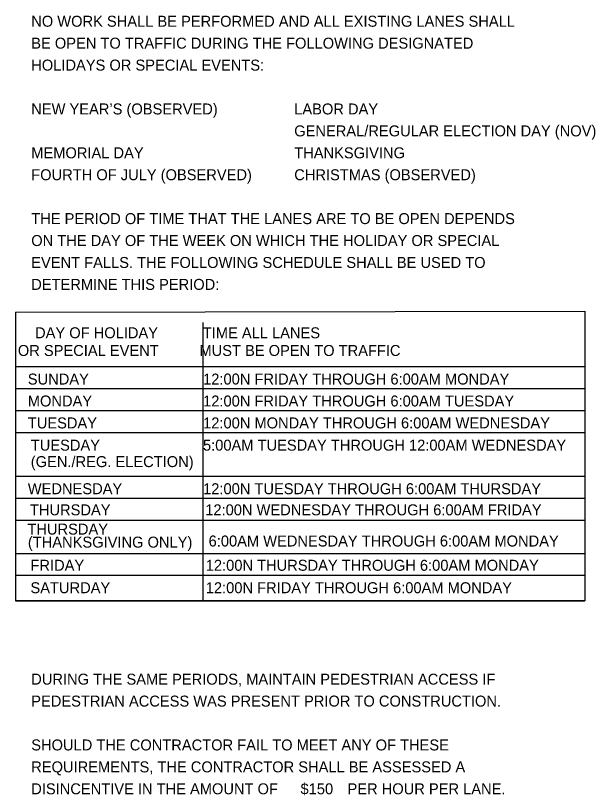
# Model space of a CAD drawing. Extents: x 0 to 34, y 0 to 33.4.
# Drawn here: x 9.62 to 17.03, y 23.47 to 33.42 of the extents above; entities that cross this region are included whole.
import ezdxf

# ---------------------------------------------------------------- set-up
doc = ezdxf.new("R2010")
doc.units = 0
doc.layers.add('TX_X_20', color=7, linetype='Continuous')

msp = doc.modelspace()

# ---------------------------------------------------------------- linework, layer by layer
at = {"layer": 'TX_X_20'}
for p, q in [((9.62, 29.6387), (9.62, 25.9535)), ((12.0162, 25.9535), (12.0162, 29.5071)), ((9.62, 28.9429), (16.8943, 28.9429)), ((9.62, 28.6629), (16.8941, 28.6629)), ((9.62, 28.3829), (16.8938, 28.3829)), ((9.62, 28.1029), (16.8931, 28.1029)), ((9.62, 27.5429), (16.8927, 27.5429)), ((9.62, 27.2629), (16.8924, 27.2629)), ((9.62, 26.9829), (16.8922, 26.9829)), ((9.62, 26.5587), (16.8918, 26.5587)), ((9.62, 26.2787), (16.8915, 26.2787)), ((9.62, 25.9535), (16.8913, 25.9535))]:
    msp.add_line(p, q, dxfattribs=at)
msp.add_lwpolyline([(9.62, 29.6387), (16.8947, 29.6515), (16.8913, 25.9535), (9.62, 25.9535)], dxfattribs=at)

# ---------------------------------------------------------------- texts
for s, p in [('NO WORK SHALL BE PERFORMED AND ALL EXISTING LANES SHALL ', (9.82, 33.2829)), ('BE OPEN TO TRAFFIC DURING THE FOLLOWING DESIGNATED ', (9.82, 33.0029)), ('HOLIDAYS OR SPECIAL EVENTS:', (9.82, 32.7229)), ('NEW YEAR’S (OBSERVED)', (9.82, 32.1629)), ('LABOR DAY', (13.18, 32.1629)), ('GENERAL/REGULAR ELECTION DAY (NOV)', (13.18, 31.8829)), ('MEMORIAL DAY', (9.82, 31.6029)), ('THANKSGIVING', (13.18, 31.6029)), ('FOURTH OF JULY (OBSERVED)', (9.82, 31.3229)), ('CHRISTMAS (OBSERVED)', (13.18, 31.3229)), ('THE PERIOD OF TIME THAT THE LANES ARE TO BE OPEN DEPENDS ', (9.82, 30.7629)), ('ON THE DAY OF THE WEEK ON WHICH THE HOLIDAY OR SPECIAL ', (9.82, 30.4829)), ('EVENT FALLS. THE FOLLOWING SCHEDULE SHALL BE USED TO ', (9.82, 30.2029)), ('DETERMINE THIS PERIOD:', (9.82, 29.9229)), ('   DAY OF HOLIDAY           TIME ALL LANES', (9.7128, 29.3054)), ('   OR SPECIAL EVENT          MUST BE OPEN TO TRAFFIC', (9.4929, 29.0793)), ('   SUNDAY     ', (9.62, 28.7144)), ('   12:00N FRIDAY THROUGH 6:00AM MONDAY', (11.86, 28.7144)), ('   MONDAY     ', (9.62, 28.4344)), ('   12:00N FRIDAY THROUGH 6:00AM TUESDAY', (11.86, 28.4344)), ('   TUESDAY    ', (9.62, 28.1544)), ('   12:00N MONDAY THROUGH 6:00AM WEDNESDAY', (11.86, 28.1544)), ('TUESDAY    ', (9.8142, 27.8705)), ('          5:00AM TUESDAY THROUGH 12:00AM WEDNESDAY', (11.4942, 27.8705)), ('(GEN./REG. ELECTION)', (9.8142, 27.6605)), ('   WEDNESDAY  ', (9.62, 27.3144)), ('   12:00N TUESDAY THROUGH 6:00AM THURSDAY', (11.86, 27.3144)), ('   THURSDAY   ', (9.6471, 27.0446)), ('   12:00N WEDNESDAY THROUGH 6:00AM FRIDAY', (11.8871, 27.0446)), ('   THURSDAY ', (9.6153, 26.7986)), ('                   6:00AM WEDNESDAY THROUGH 6:00AM MONDAY', (11.0981, 26.6466)), ('(THANKSGIVING ONLY)', (9.7771, 26.6325)), ('   FRIDAY    ', (9.6539, 26.337)), ('   12:00N THURSDAY THROUGH 6:00AM MONDAY', (11.8939, 26.337)), ('   SATURDAY   ', (9.6539, 26.0502)), ('   12:00N FRIDAY THROUGH 6:00AM MONDAY', (11.8939, 26.0502)), ('DURING THE SAME PERIODS, MAINTAIN PEDESTRIAN ACCESS IF ', (9.82, 24.8829)), ('PEDESTRIAN ACCESS WAS PRESENT PRIOR TO CONSTRUCTION.', (9.82, 24.6029)), ('SHOULD THE CONTRACTOR FAIL TO MEET ANY OF THESE ', (9.82, 24.0429)), ('REQUIREMENTS, THE CONTRACTOR SHALL BE ASSESSED A ', (9.82, 23.7629)), ('DISINCENTIVE IN THE AMOUNT OF ', (9.82, 23.4829)), ('  $150  ', (13.1566, 23.4829)), (' PER HOUR PER LANE.', (13.8088, 23.4829))]:
    msp.add_text(s, height=0.14, dxfattribs=at).set_placement(p)

doc.saveas('drawing.dxf')
